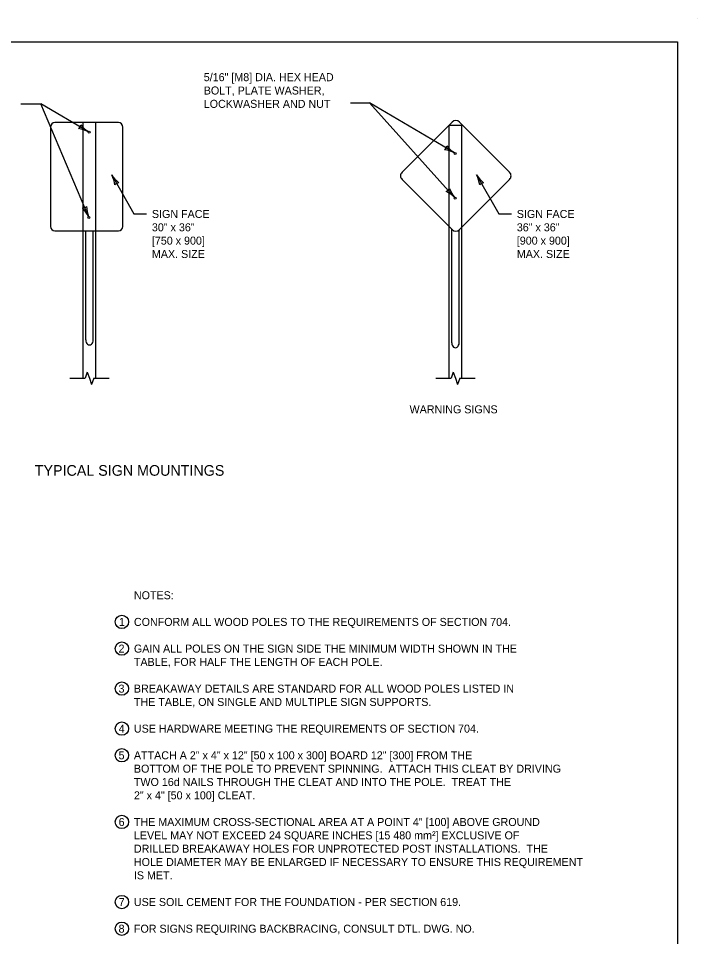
# Model space of a CAD drawing. Extents: x 49991.4 to 50021, y 49987.6 to 50011.4.
# Drawn here: x 50011.81 to 50016.9, y 49992.29 to 49999.18 of the extents above; entities that cross this region are included whole.
import ezdxf

# ---------------------------------------------------------------- set-up
doc = ezdxf.new("R2010")
doc.units = 0
for name, color, linetype in [('Level 1', 7, 'Continuous'), ('Level 2', 7, 'Continuous'), ('Level 3', 7, 'Continuous'), ('Level 4', 7, 'Continuous'), ('Level 6', 7, 'Continuous')]:
    doc.layers.add(name, color=color, linetype=linetype)

msp = doc.modelspace()

# ---------------------------------------------------------------- linework, layer by layer
at = {"layer": 'Level 1'}
for p, q in [((50016.9001, 49999.1756), (50016.9001, 49999.1756)), ((50012.0491, 49998.3601), (50012.0491, 49997.6156)), ((50012.5591, 49998.3941), (50012.0831, 49998.3941)), ((50012.5931, 49997.6156), (50012.5931, 49998.3601)), ((50015.0607, 49998.3981), (50014.6844, 49998.0217)), ((50015.4909, 49998.0217), (50015.1145, 49998.3981)), ((50014.6844, 49997.968), (50015.0607, 49997.5916)), ((50015.4222, 49997.8993), (50015.4909, 49997.968)), ((50015.1145, 49997.5916), (50015.4222, 49997.8994)), ((50015.037, 49996.4774), (50015.037, 49997.6153)), ((50015.0568, 49996.7427), (50015.0568, 49997.5955)), ((50015.1128, 49996.7427), (50015.1128, 49997.59)), ((50015.1322, 49996.4774), (50015.1322, 49997.6093)), ((50012.0831, 49997.5816), (50012.5591, 49997.5816)), ((50012.2942, 49996.4774), (50012.2942, 49997.5816)), ((50012.314, 49996.7647), (50012.314, 49997.5816)), ((50012.37, 49996.7647), (50012.37, 49997.5816)), ((50012.3894, 49996.4774), (50012.3894, 49997.5816))]:
    msp.add_line(p, q, dxfattribs=at)
msp.add_lwpolyline([(49999.3835, 49998.9992), (50016.7501, 49998.9992), (50016.7501, 49987.7988), (49999.3835, 49987.7988)], close=True, dxfattribs=at)
for centre in [(50012.3405, 49998.3215), (50015.0838, 49998.163), (50015.0838, 49997.8272), (50012.3373, 49997.683)]:
    msp.add_circle(centre, 0.0072, dxfattribs=at)
for centre, radius, start, end in [((50012.0831, 49998.3601), 0.034, 90, 180), ((50012.5591, 49998.3601), 0.034, 0, 90), ((50015.0876, 49998.3712), 0.038, 45.00008, 134.99993), ((50014.7113, 49997.9948), 0.038, 134.99993, 225.00008), ((50015.464, 49997.9948), 0.038, 314.99993, 45.00008), ((50012.0831, 49997.6156), 0.034, 180, 270), ((50012.5591, 49997.6156), 0.034, 270, 0), ((50015.0876, 49997.6185), 0.038, 225.00007, 314.99993)]:
    msp.add_arc(centre, radius, start, end, dxfattribs=at)
for centre in [(50012.342, 49996.7647), (50015.0848, 49996.7427)]:
    msp.add_ellipse(centre, major_axis=(0, -0.0368), ratio=0.761048, start_param=4.712389, end_param=7.853982, dxfattribs=at)
at = {"layer": 'Level 2'}
for centre in [(50012.5851, 49994.6504), (50012.5851, 49994.4504), (50012.5851, 49994.1504), (50012.5851, 49993.8504), (50012.5851, 49993.6504), (50012.5851, 49993.1504), (50012.5851, 49992.5504), (50012.5851, 49992.3504)]:
    msp.add_circle(centre, 0.05, dxfattribs=at)
at = {"layer": 'Level 3'}
for p, q in [((50011.8271, 49998.5347), (50011.9784, 49998.5347)), ((50012.3343, 49998.3251), (50011.9784, 49998.5347)), ((50012.3345, 49997.6896), (50011.9784, 49998.5347)), ((50014.2978, 49998.5429), (50014.4409, 49998.5429)), ((50015.0776, 49998.1667), (50014.4409, 49998.5429)), ((50015.079, 49997.8326), (50014.4409, 49998.5429)), ((50012.5086, 49998.0013), (50012.6751, 49997.7091)), ((50015.2437, 49998.0013), (50015.4102, 49997.7091)), ((50012.6751, 49997.7091), (50012.7699, 49997.7091)), ((50015.4102, 49997.7091), (50015.505, 49997.7091))]:
    msp.add_line(p, q, dxfattribs=at)
for centre, radius, start, end in [((50012.2238, 49998.3902), 0.0548, 311.64977, 347.37213), ((50012.2261, 49998.1188), 0.233, 62.33826, 81.58811), ((50012.4549, 49998.5119), 0.2223, 216.96696, 237.15047), ((50014.9672, 49998.2319), 0.0548, 311.56172, 347.28408), ((50015.1985, 49998.3533), 0.2223, 216.87891, 237.06242), ((50014.9691, 49997.9605), 0.233, 62.25021, 81.50006), ((50012.3111, 49997.8993), 0.2223, 7.13116, 27.31467), ((50012.7051, 49998.1265), 0.233, 212.50246, 231.75231), ((50015.0462, 49997.8993), 0.2223, 7.13116, 27.31467), ((50015.4402, 49998.1265), 0.233, 212.50246, 231.75231), ((50012.5721, 49997.8899), 0.0548, 101.81397, 137.53633), ((50015.3072, 49997.8899), 0.0548, 101.81397, 137.53633), ((50014.9933, 49997.9279), 0.0548, 294.07385, 329.79621), ((50014.9136, 49997.6685), 0.233, 44.76234, 64.01219), ((50015.2504, 49997.9742), 0.2223, 199.39104, 219.57455), ((50012.2847, 49997.8078), 0.0548, 274.98901, 310.71137), ((50012.1245, 49997.5887), 0.233, 25.6775, 44.92735), ((50012.5428, 49997.7674), 0.2223, 180.3062, 200.48971)]:
    msp.add_arc(centre, radius, start, end, dxfattribs=at)
at = {"layer": 'Level 4'}
for p, q in [((50012.2942, 49997.5816), (50012.2942, 49998.3941)), ((50012.3894, 49997.5816), (50012.3894, 49998.3941)), ((50015.037, 49997.6153), (50015.037, 49998.3744)), ((50015.037, 49998.3744), (50015.1324, 49998.3744)), ((50015.1322, 49997.6093), (50015.1322, 49998.3744))]:
    msp.add_line(p, q, dxfattribs=at)
at = {"layer": 'Level 6'}
for p, q in [((50012.3256, 49996.5231), (50012.3094, 49996.4774)), ((50012.3256, 49996.5231), (50012.3418, 49996.4774)), ((50015.0684, 49996.5231), (50015.0522, 49996.4774)), ((50015.0684, 49996.5231), (50015.0846, 49996.4774)), ((50012.1942, 49996.4774), (50012.3094, 49996.4774)), ((50012.3418, 49996.4774), (50012.358, 49996.4317)), ((50012.3742, 49996.4774), (50012.358, 49996.4317)), ((50012.3742, 49996.4774), (50012.4894, 49996.4774)), ((50014.937, 49996.4774), (50015.0522, 49996.4774)), ((50015.0846, 49996.4774), (50015.1008, 49996.4317)), ((50015.117, 49996.4774), (50015.1008, 49996.4317)), ((50015.117, 49996.4774), (50015.2322, 49996.4774))]:
    msp.add_line(p, q, dxfattribs=at)

# ---------------------------------------------------------------- texts
at = {"layer": 'Level 2'}
for s, height, p in [('5/16" [M8] DIA. HEX HEAD', 0.06, (50013.1986, 49998.7047)), ('BOLT, PLATE WASHER,', 0.06, (50013.1986, 49998.6047)), ('LOCKWASHER AND NUT', 0.06, (50013.1986, 49998.5047)), ('SIGN FACE', 0.06, (50012.8099, 49997.6791)), ('SIGN FACE', 0.06, (50015.545, 49997.6791)), ('30" x 36"', 0.06, (50012.8099, 49997.5791)), ('36" x 36"', 0.06, (50015.545, 49997.5791)), ('[750 x 900]', 0.06, (50012.8099, 49997.4791)), ('[900 x 900]', 0.06, (50015.545, 49997.4791)), ('MAX. SIZE', 0.06, (50012.8099, 49997.3791)), ('MAX. SIZE', 0.06, (50015.545, 49997.3791)), ('WARNING SIGNS', 0.06, (50014.7411, 49996.2144)), ('TYPICAL SIGN MOUNTINGS', 0.08, (50011.9321, 49995.7463)), ('NOTES:', 0.06, (50012.6751, 49994.8204)), ('1', 0.06, (50012.5624, 49994.6204)), ('CONFORM ALL WOOD POLES TO THE REQUIREMENTS OF SECTION 704.', 0.06, (50012.6751, 49994.6204)), ('2', 0.06, (50012.5599, 49994.4204)), ('GAIN ALL POLES ON THE SIGN SIDE THE MINIMUM WIDTH SHOWN IN THE', 0.06, (50012.6751, 49994.4204)), ('TABLE, FOR HALF THE LENGTH OF EACH POLE.', 0.06, (50012.6751, 49994.3204)), ('3', 0.06, (50012.5599, 49994.1204)), ('BREAKAWAY DETAILS ARE STANDARD FOR ALL WOOD POLES LISTED IN', 0.06, (50012.6751, 49994.1204)), ('THE TABLE, ON SINGLE AND MULTIPLE SIGN SUPPORTS.', 0.06, (50012.6751, 49994.0204)), ('4', 0.06, (50012.5611, 49993.8204)), ('USE HARDWARE MEETING THE REQUIREMENTS OF SECTION 704.', 0.06, (50012.6751, 49993.8204)), ('5', 0.06, (50012.5602, 49993.6204)), ('ATTACH A 2" x 4" x 12" [50 x 100 x 300] BOARD 12" [300] FROM THE', 0.06, (50012.6751, 49993.6204)), ('BOTTOM OF THE POLE TO PREVENT SPINNING.  ATTACH THIS CLEAT BY DRIVING', 0.06, (50012.6751, 49993.5204)), ('TWO 16d NAILS THROUGH THE CLEAT AND INTO THE POLE.  TREAT THE ', 0.06, (50012.6751, 49993.4204)), ('2" x 4" [50 x 100] CLEAT.', 0.06, (50012.6751, 49993.3204)), ('6', 0.06, (50012.5606, 49993.1204)), ('THE MAXIMUM CROSS-SECTIONAL AREA AT A POINT 4" [100] ABOVE GROUND ', 0.06, (50012.6751, 49993.1204)), ('LEVEL MAY NOT EXCEED 24 SQUARE INCHES [15 480 mm²] EXCLUSIVE OF', 0.06, (50012.6751, 49993.0204)), ('DRILLED BREAKAWAY HOLES FOR UNPROTECTED POST INSTALLATIONS.  THE', 0.06, (50012.6751, 49992.9204)), ('HOLE DIAMETER MAY BE ENLARGED IF NECESSARY TO ENSURE THIS REQUIREMENT ', 0.06, (50012.6751, 49992.8204)), ('IS MET.', 0.06, (50012.6751, 49992.7204)), ('7', 0.06, (50012.5613, 49992.5204)), ('USE SOIL CEMENT FOR THE FOUNDATION - PER SECTION 619.', 0.06, (50012.6751, 49992.5204)), ('8', 0.06, (50012.5601, 49992.3204)), ('FOR SIGNS REQUIRING BACKBRACING, CONSULT DTL. DWG. NO.', 0.06, (50012.6751, 49992.3204))]:
    msp.add_text(s, height=height, dxfattribs=at).set_placement(p)

doc.saveas('drawing.dxf')
